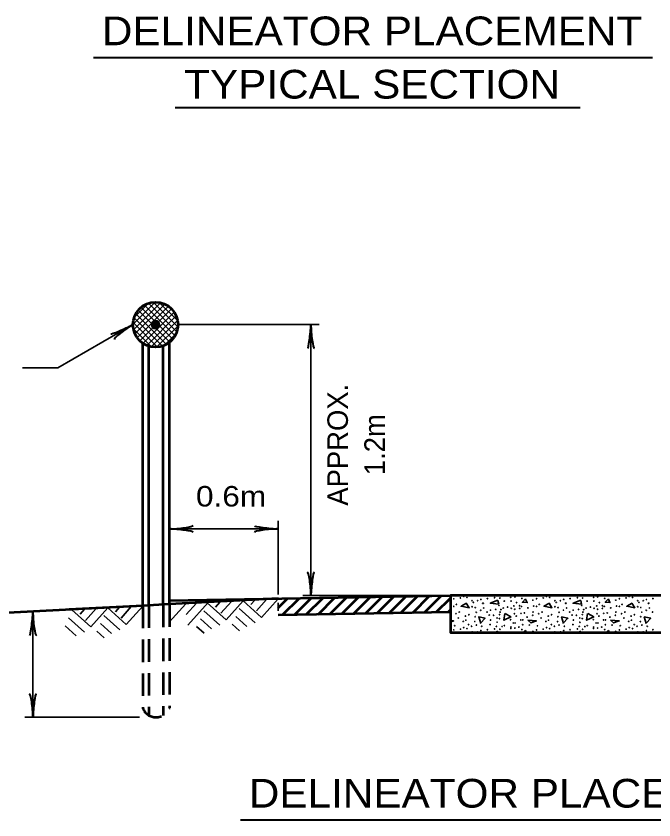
# Model space of a CAD drawing. Extents: x -89 to 766, y -60 to 484.
# Drawn here: x 47 to 140.2, y 231.2 to 348.8 of the extents above; entities that cross this region are included whole.
import ezdxf
from ezdxf.enums import TextEntityAlignment as Align

# ---------------------------------------------------------------- set-up
doc = ezdxf.new("R2010")
doc.units = 0
doc.header["$LTSCALE"] = 1.1
doc.linetypes.add('MEDIUM_DASHED', pattern=[4.5, 3, -1.5])
doc.layers.add('1', color=7, linetype='Continuous', lineweight=35)

msp = doc.modelspace()

# ---------------------------------------------------------------- hatches: boundary and pattern name
at = {"layer": '1'}
msp.add_hatch(color=256, dxfattribs=at).paths.add_polyline_path([(68.019, 303.675, 1), (66.819, 303.675, 1)])

# ---------------------------------------------------------------- linework, layer by layer
at = {"layer": '1', "lineweight": 40}
for p, q in [((58.353, 342.741), (140.025, 342.741)), ((70.295, 335.41), (129.491, 335.41)), ((79.824, 231.246), (161.496, 231.246))]:
    msp.add_line(p, q, dxfattribs=at)
at = {"layer": '1'}
for p, q in [((64.12, 303.709), (67.384, 306.972)), ((64.204, 302.943), (68.15, 306.889)), ((70.698, 303.348), (67.091, 306.955)), ((70.667, 304.228), (67.972, 306.922)), ((64.301, 304.738), (66.357, 306.794)), ((64.42, 302.312), (68.782, 306.673)), ((64.728, 301.771), (69.324, 306.367)), ((69.518, 301.134), (64.879, 305.773)), ((65.12, 301.315), (69.779, 305.973)), ((69.944, 301.557), (65.301, 306.2)), ((70.292, 302.057), (65.803, 306.546)), ((70.549, 302.648), (66.392, 306.805)), ((69.923, 305.82), (69.567, 306.177)), ((68.419, 300.536), (64.281, 304.674)), ((69.013, 300.79), (64.534, 305.27)), ((65.588, 300.934), (70.161, 305.507)), ((66.14, 300.637), (70.456, 304.953)), ((67.715, 300.392), (64.137, 303.969)), ((66.792, 300.441), (70.653, 304.302)), ((67.585, 300.385), (70.71, 303.51)), ((70.719, 303.675), (91.323, 303.675)), ((90.123, 264.048), (90.123, 303.675)), ((66.823, 300.435), (64.18, 303.078)), ((68.678, 300.63), (70.468, 302.42)), ((85.327, 264.208), (85.327, 275.008)), ((85.327, 273.808), (69.454, 273.808)), ((81.926, 263.382), (81.335, 262.726)), ((83.651, 263.472), (82.153, 261.808)), ((85.353, 263.561), (82.923, 260.863)), ((108.123, 264.048), (88.923, 264.048)), ((58.75, 262.167), (57.183, 260.427)), ((60.451, 262.256), (57.977, 259.483)), ((60.451, 262.256), (63.15, 259.826)), ((62.153, 262.345), (61.562, 261.69)), ((63.879, 262.436), (62.38, 260.771)), ((65.58, 262.525), (63.15, 259.826)), ((71.86, 262.854), (69.43, 260.155)), ((73.394, 262.935), (71.895, 261.27)), ((75.095, 263.024), (72.12, 259.72)), ((74.975, 263.018), (77.75, 260.519)), ((76.797, 263.113), (76.162, 262.383)), ((78.523, 263.203), (76.955, 261.463)), ((80.224, 263.293), (77.75, 260.519)), ((79.657, 262.181), (81.978, 260.092)), ((80.224, 263.293), (82.923, 260.863)), ((85.327, 263.008), (85.327, 261.808)), ((49.504, 246.257), (49.504, 261.668)), ((55.202, 261.981), (57.977, 259.483)), ((57.024, 262.077), (56.389, 261.346)), ((59.885, 261.145), (62.205, 259.056)), ((74.46, 261.837), (76.805, 259.749)), ((79.166, 261.002), (80.781, 259.549)), ((54.688, 260.801), (57.032, 258.712)), ((59.394, 259.966), (61.008, 258.512)), ((73.969, 260.658), (75.584, 259.204)), ((78.601, 259.867), (79.686, 258.89)), ((54.197, 259.621), (55.811, 258.168)), ((58.828, 258.831), (59.913, 257.854)), ((73.428, 259.524), (74.511, 258.571)), ((117.456, 258.827), (117.012, 258.648)), ((117.484, 258.648), (117.456, 258.779)), ((121.488, 258.995), (121.158, 258.648)), ((121.637, 258.648), (121.488, 258.947)), ((129.552, 258.827), (129.108, 258.648)), ((129.58, 258.648), (129.552, 258.779)), ((133.584, 258.995), (133.254, 258.648)), ((133.733, 258.648), (133.584, 258.947)), ((65.104, 246.257), (48.304, 246.257))]:
    msp.add_line(p, q, dxfattribs=at)
at = {"layer": '1', "lineweight": 53}
for p, q in [((65.554, 262.572), (65.554, 300.953)), ((69.454, 262.776), (69.454, 301.077)), ((66.454, 262.619), (66.454, 300.519)), ((68.554, 262.729), (68.554, 300.576)), ((69.454, 263.331), (110.523, 264.048)), ((85.327, 262.245), (86.714, 263.632)), ((85.998, 261.219), (88.441, 263.663)), ((87.725, 261.25), (90.169, 263.693)), ((89.453, 261.28), (91.896, 263.723)), ((91.18, 261.31), (93.623, 263.753)), ((92.907, 261.34), (95.35, 263.783)), ((94.634, 261.37), (97.077, 263.813)), ((96.362, 261.4), (98.805, 263.843)), ((98.089, 261.43), (100.532, 263.874)), ((99.816, 261.461), (102.259, 263.904)), ((101.543, 261.491), (103.986, 263.934)), ((103.27, 261.521), (105.713, 263.964)), ((104.998, 261.551), (107.441, 263.994)), ((106.725, 261.581), (109.168, 264.024)), ((108.452, 261.611), (110.523, 263.682)), ((65.554, 262.572), (18.818, 260.122)), ((110.523, 261.648), (85.327, 261.208)), ((110.179, 261.642), (110.523, 261.985))]:
    msp.add_line(p, q, dxfattribs=at)
at = {"layer": '1', "linetype": 'MEDIUM_DASHED', "lineweight": 53}
for p, q in [((65.554, 262.572), (65.554, 247.572)), ((66.454, 262.619), (66.454, 246.538)), ((68.554, 262.729), (68.554, 246.538)), ((69.454, 262.776), (69.454, 247.572))]:
    msp.add_line(p, q, dxfattribs=at)
at = {"layer": '1'}
for points in [[(64.119, 303.675), (53.169, 297.371), (47.978, 297.371)], [(117.456, 263.387), (116.328, 262.931), (117.576, 262.787), (117.456, 263.339)], [(121.488, 263.555), (121.032, 263.075), (121.728, 263.027), (121.488, 263.507)], [(129.552, 263.387), (128.424, 262.931), (129.672, 262.787), (129.552, 263.339)], [(133.584, 263.555), (133.128, 263.075), (133.824, 263.027), (133.584, 263.507)], [(112.872, 262.931), (112.08, 262.499), (113.256, 262.283), (112.824, 262.955)], [(124.968, 262.931), (124.176, 262.499), (125.352, 262.283), (124.92, 262.955)], [(137.064, 262.931), (136.272, 262.499), (137.448, 262.283), (137.016, 262.955)], [(118.512, 261.419), (119.352, 260.939), (118.32, 260.435), (118.464, 261.443)], [(130.608, 261.419), (131.448, 260.939), (130.416, 260.435), (130.56, 261.443)], [(110.523, 260.392), (110.976, 260.339), (110.523, 260.179)], [(114.936, 259.979), (114.648, 260.939), (115.584, 260.747), (114.912, 260.027)], [(127.032, 259.979), (126.744, 260.939), (127.68, 260.747), (127.008, 260.027)], [(139.128, 259.979), (138.84, 260.939), (139.776, 260.747), (139.104, 260.027)]]:
    msp.add_lwpolyline(points, dxfattribs=at)
at = {"layer": '1', "lineweight": 53}
for points in [[(85.327, 263.608), (69.454, 262.776), (65.554, 262.572), (54.783, 262.007)], [(196.323, 264.048), (110.523, 264.048), (110.523, 261.648), (110.523, 258.648), (196.323, 258.648)]]:
    msp.add_lwpolyline(points, dxfattribs=at)
at = {"layer": '1'}
for points in [[(121.824, 260.483), (123.072, 260.339), (122.256, 260.051)], [(133.92, 260.483), (135.168, 260.339), (134.352, 260.051)]]:
    msp.add_lwpolyline(points, close=True, dxfattribs=at)
at = {"layer": '1', "lineweight": 53}
msp.add_circle((67.419, 303.675), 3.3, dxfattribs=at)
at = {"layer": '1'}
for centre, radius in [((67.419, 303.675), 0.6), ((111.009, 263.592), 0.0318), ((111.98, 263.703), 0.0318), ((112.457, 263.936), 0.0318), ((112.934, 263.783), 0.0318), ((113.681, 263.306), 0.0318), ((114.492, 263.306), 0.0318), ((114.969, 263.497), 0.0318), ((115.908, 263.624), 0.0318), ((116.973, 263.735), 0.0318), ((117.737, 263.687), 0.0318), ((119.327, 263.799), 0.0318), ((119.343, 264), 0.0318), ((119.931, 263.862), 0.0318), ((120.52, 264.016), 0.0318), ((120.958, 263.64), 0.0318), ((122.565, 263.385), 0.0318), ((123.105, 263.592), 0.0318), ((124.076, 263.703), 0.0318), ((124.553, 263.936), 0.0318), ((125.03, 263.783), 0.0318), ((125.777, 263.306), 0.0318), ((126.588, 263.306), 0.0318), ((127.065, 263.497), 0.0318), ((128.004, 263.624), 0.0318), ((129.069, 263.735), 0.0318), ((129.833, 263.687), 0.0318), ((131.423, 263.799), 0.0318), ((131.439, 264), 0.0318), ((132.027, 263.862), 0.0318), ((132.616, 264.016), 0.0318), ((133.054, 263.64), 0.0318), ((134.661, 263.385), 0.0318), ((135.201, 263.592), 0.0318), ((136.172, 263.703), 0.0318), ((136.649, 263.936), 0.0318), ((137.126, 263.783), 0.0318), ((137.873, 263.306), 0.0318), ((138.684, 263.306), 0.0318), ((139.161, 263.497), 0.0318), ((140.1, 263.624), 0.0318), ((110.596, 262.526), 0.0318), ((111.009, 262.478), 0.0318), ((111.391, 262.765), 0.0318), ((113.681, 262.415), 0.0318), ((113.872, 263.051), 0.0318), ((114.142, 262.303), 0.0318), ((115.24, 262.94), 0.0318), ((115.303, 262.94), 0.0318), ((115.383, 262.24), 0.0318), ((117.609, 262.622), 0.0318), ((118.23, 262.224), 0.0318), ((118.373, 263.242), 0.0318), ((118.866, 262.367), 0.0318), ((119.375, 263.258), 0.0318), ((119.407, 262.192), 0.0318), ((119.788, 262.542), 0.0318), ((120.186, 263.035), 0.0318), ((120.615, 262.558), 0.0318), ((120.631, 262.176), 0.0318), ((120.895, 262.463), 0.0318), ((121.833, 262.256), 0.0318), ((122.692, 262.526), 0.0318), ((123.105, 262.478), 0.0318), ((123.487, 262.765), 0.0318), ((125.777, 262.415), 0.0318), ((125.968, 263.051), 0.0318), ((126.238, 262.303), 0.0318), ((127.336, 262.94), 0.0318), ((127.399, 262.94), 0.0318), ((127.479, 262.24), 0.0318), ((129.705, 262.622), 0.0318), ((130.326, 262.224), 0.0318), ((130.469, 263.242), 0.0318), ((130.962, 262.367), 0.0318), ((131.471, 263.258), 0.0318), ((131.503, 262.192), 0.0318), ((131.884, 262.542), 0.0318), ((132.282, 263.035), 0.0318), ((132.711, 262.558), 0.0318), ((132.727, 262.176), 0.0318), ((132.991, 262.463), 0.0318), ((133.929, 262.256), 0.0318), ((134.788, 262.526), 0.0318), ((135.201, 262.478), 0.0318), ((135.583, 262.765), 0.0318), ((137.873, 262.415), 0.0318), ((138.064, 263.051), 0.0318), ((138.334, 262.303), 0.0318), ((139.432, 262.94), 0.0318), ((139.495, 262.94), 0.0318), ((139.575, 262.24), 0.0318), ((111.327, 261.397), 0.0318), ((111.805, 261.651), 0.0318), ((112.711, 261.047), 0.0318), ((113.204, 261.253), 0.0318), ((114.127, 260.967), 0.0318), ((114.286, 261.619), 0.0318), ((114.938, 261.906), 0.0318), ((115.86, 261.651), 0.0318), ((116.194, 261.206), 0.0318), ((116.353, 261.922), 0.0318), ((116.814, 261.174), 0.0318), ((117.132, 262.033), 0.0318), ((117.689, 261.269), 0.0318), ((117.769, 261.635), 0.0318), ((117.896, 262.017), 0.0318), ((119.852, 261.397), 0.0318), ((119.916, 262.065), 0.0318), ((120.122, 261.047), 0.0318), ((120.822, 261.46), 0.0318), ((121.324, 261.524), 0.0318), ((122.533, 261.174), 0.0318), ((122.596, 261.651), 0.0318), ((123.423, 261.397), 0.0318), ((123.901, 261.651), 0.0318), ((124.807, 261.047), 0.0318), ((125.3, 261.253), 0.0318), ((126.223, 260.967), 0.0318), ((126.382, 261.619), 0.0318), ((127.034, 261.906), 0.0318), ((127.956, 261.651), 0.0318), ((128.29, 261.206), 0.0318), ((128.449, 261.922), 0.0318), ((128.91, 261.174), 0.0318), ((129.228, 262.033), 0.0318), ((129.785, 261.269), 0.0318), ((129.865, 261.635), 0.0318), ((129.992, 262.017), 0.0318), ((131.948, 261.397), 0.0318), ((132.012, 262.065), 0.0318), ((132.218, 261.047), 0.0318), ((132.918, 261.46), 0.0318), ((133.42, 261.524), 0.0318), ((134.629, 261.174), 0.0318), ((134.692, 261.651), 0.0318), ((135.519, 261.397), 0.0318), ((135.997, 261.651), 0.0318), ((136.903, 261.047), 0.0318), ((137.396, 261.253), 0.0318), ((138.319, 260.967), 0.0318), ((138.478, 261.619), 0.0318), ((139.13, 261.906), 0.0318), ((140.052, 261.651), 0.0318), ((111.661, 260.776), 0.0318), ((112.377, 260.283), 0.0318), ((112.759, 260.458), 0.0318), ((113.172, 259.806), 0.0318), ((114.079, 260.251), 0.0318), ((116.305, 259.822), 0.0318), ((116.385, 260.474), 0.0318), ((117.323, 260.776), 0.0318), ((117.339, 260.156), 0.0318), ((117.673, 260.697), 0.0318), ((119.295, 260.522), 0.0318), ((119.693, 260.044), 0.0318), ((119.963, 260.044), 0.0318), ((120.798, 260.487), 0.0318), ((121.07, 260.506), 0.0318), ((121.07, 259.79), 0.0318), ((121.722, 260.903), 0.0318), ((123.757, 260.776), 0.0318), ((124.473, 260.283), 0.0318), ((124.855, 260.458), 0.0318), ((125.268, 259.806), 0.0318), ((126.175, 260.251), 0.0318), ((128.401, 259.822), 0.0318), ((128.481, 260.474), 0.0318), ((129.419, 260.776), 0.0318), ((129.435, 260.156), 0.0318), ((129.769, 260.697), 0.0318), ((131.391, 260.522), 0.0318), ((131.789, 260.044), 0.0318), ((132.059, 260.044), 0.0318), ((132.894, 260.487), 0.0318), ((133.166, 260.506), 0.0318), ((133.166, 259.79), 0.0318), ((133.818, 260.903), 0.0318), ((135.853, 260.776), 0.0318), ((136.569, 260.283), 0.0318), ((136.951, 260.458), 0.0318), ((137.364, 259.806), 0.0318), ((138.271, 260.251), 0.0318), ((111.009, 259.032), 0.0318), ((111.137, 259.647), 0.0318), ((111.98, 259.143), 0.0318), ((112.457, 259.376), 0.0318), ((112.934, 259.223), 0.0318), ((113.602, 259.567), 0.0318), ((113.681, 258.746), 0.0318), ((114.301, 259.742), 0.0318), ((114.492, 258.746), 0.0318), ((114.969, 258.937), 0.0318), ((115.081, 259.567), 0.0318), ((115.908, 259.064), 0.0318), ((116.973, 259.175), 0.0318), ((117.228, 259.551), 0.0318), ((117.737, 259.127), 0.0318), ((118.071, 259.519), 0.0318), ((118.373, 258.682), 0.0318), ((118.405, 259.663), 0.0318), ((119.327, 259.239), 0.0318), ((119.343, 259.44), 0.0318), ((119.375, 258.698), 0.0318), ((119.931, 259.302), 0.0318), ((120.52, 259.456), 0.0318), ((120.958, 259.08), 0.0318), ((122.04, 259.742), 0.0318), ((122.565, 258.825), 0.0318), ((123.105, 259.032), 0.0318), ((123.233, 259.647), 0.0318), ((124.076, 259.143), 0.0318), ((124.553, 259.376), 0.0318), ((125.03, 259.223), 0.0318), ((125.698, 259.567), 0.0318), ((125.777, 258.746), 0.0318), ((126.397, 259.742), 0.0318), ((126.588, 258.746), 0.0318), ((127.065, 258.937), 0.0318), ((127.177, 259.567), 0.0318), ((128.004, 259.064), 0.0318), ((129.069, 259.175), 0.0318), ((129.324, 259.551), 0.0318), ((129.833, 259.127), 0.0318), ((130.167, 259.519), 0.0318), ((130.469, 258.682), 0.0318), ((130.501, 259.663), 0.0318), ((131.423, 259.239), 0.0318), ((131.439, 259.44), 0.0318), ((131.471, 258.698), 0.0318), ((132.027, 259.302), 0.0318), ((132.616, 259.456), 0.0318), ((133.054, 259.08), 0.0318), ((134.136, 259.742), 0.0318), ((134.661, 258.825), 0.0318), ((135.201, 259.032), 0.0318), ((135.329, 259.647), 0.0318), ((136.172, 259.143), 0.0318), ((136.649, 259.376), 0.0318), ((137.126, 259.223), 0.0318), ((137.794, 259.567), 0.0318), ((137.873, 258.746), 0.0318), ((138.493, 259.742), 0.0318), ((138.684, 258.746), 0.0318), ((139.161, 258.937), 0.0318), ((139.273, 259.567), 0.0318), ((140.1, 259.064), 0.0318)]:
    msp.add_circle(centre, radius, dxfattribs=at)
for centre, start, end in [((118.071, 264.079), 262.28656, 277.71344), ((130.167, 264.079), 262.28656, 277.71344), ((110.5, 261.651), 314.79633, 45.20368)]:
    msp.add_arc(centre, 0.0318, start, end, dxfattribs=at)
at = {"layer": '1', "linetype": 'MEDIUM_DASHED', "lineweight": 53}
msp.add_arc((67.504, 248.36), 2.103, 202.01371, 337.98629, dxfattribs=at)
at = {"layer": '1', "lineweight": 40}
for centre, major_axis, ratio, start_param, end_param in [((62.827, 303.224), (1.932, 0.869), 0.07063, 3.1407148, 5.41811), ((62.827, 303.224), (1.932, 0.869), 0.07063, 3.1407148, 5.41811), ((63.15, 302.734), (1.764, 1.231), 0.122415, 0.8963533, 3.1415927), ((63.15, 302.734), (1.764, 1.231), 0.122415, 0.8963533, 3.1415927), ((89.869, 302.33), (0.211, 2.108), 0.07063, 3.1407148, 5.41811), ((90.454, 302.365), (-0.187, 2.143), 0.122415, 0.8963533, 3.1415927), ((70.763, 274.14), (-2.143, -0.187), 0.122415, 0.8963533, 3.1415927), ((83.982, 274.062), (2.108, -0.211), 0.07063, 3.1407148, 5.41811), ((70.798, 273.554), (-2.108, 0.211), 0.07063, 3.1407148, 5.41811), ((84.017, 273.477), (2.143, 0.187), 0.122415, 0.8963533, 3.1415927), ((89.791, 265.357), (0.187, -2.143), 0.122415, 0.8963533, 3.1415927), ((90.377, 265.393), (-0.211, -2.108), 0.07063, 3.1407148, 5.41811), ((49.25, 260.323), (0.211, 2.108), 0.07063, 3.1407148, 5.41811), ((49.25, 260.323), (0.211, 2.108), 0.07063, 3.1407148, 5.41811), ((49.835, 260.358), (-0.187, 2.143), 0.122415, 0.8963533, 3.1415927), ((49.835, 260.358), (-0.187, 2.143), 0.122415, 0.8963533, 3.1415927), ((49.172, 247.566), (0.187, -2.143), 0.122415, 0.8963533, 3.1415927), ((49.758, 247.601), (-0.211, -2.108), 0.07063, 3.1407148, 5.41811)]:
    msp.add_ellipse(centre, major_axis=major_axis, ratio=ratio, start_param=start_param, end_param=end_param, dxfattribs=at)

# ---------------------------------------------------------------- texts
at = {"layer": '1', "width": 1.1}
for s, p in [('DELINEATOR PLACEMENT', (99.063, 344.541)), ('TYPICAL SECTION', (99.063, 336.741)), ('DELINEATOR PLACEMENT', (120.534, 233.046))]:
    msp.add_text(s, height=4.2, dxfattribs=at).set_placement(p, align=Align.CENTER)
at = {"layer": '1'}
for s, p in [('APPROX.', (95.532, 286.119)), ('1.2m', (100.932, 286.12))]:
    msp.add_text(s, height=3, rotation=90, dxfattribs=at).set_placement(p, align=Align.CENTER)
at = {"layer": '1', "width": 1.15}
msp.add_text('0.6m', height=3, dxfattribs=at).set_placement((73.335, 277.081))

doc.saveas('drawing.dxf')
